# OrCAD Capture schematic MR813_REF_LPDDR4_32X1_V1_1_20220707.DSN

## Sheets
1 SOC: size A3; title: R818_REF_LPDDR4_32bitx1; rev: 0.1; note: SOC
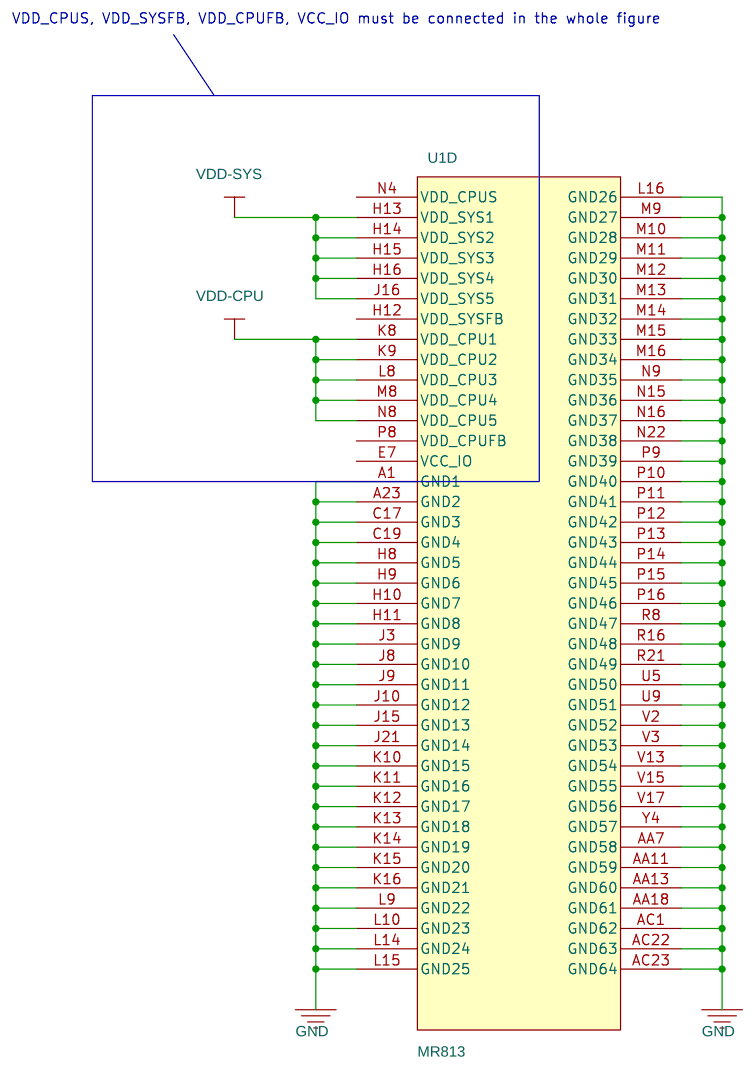
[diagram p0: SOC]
2 LPDDR4 32X1: size A3; title: A818_REF_LPDDR4_32bitx1; note: LPDDR4 32X1
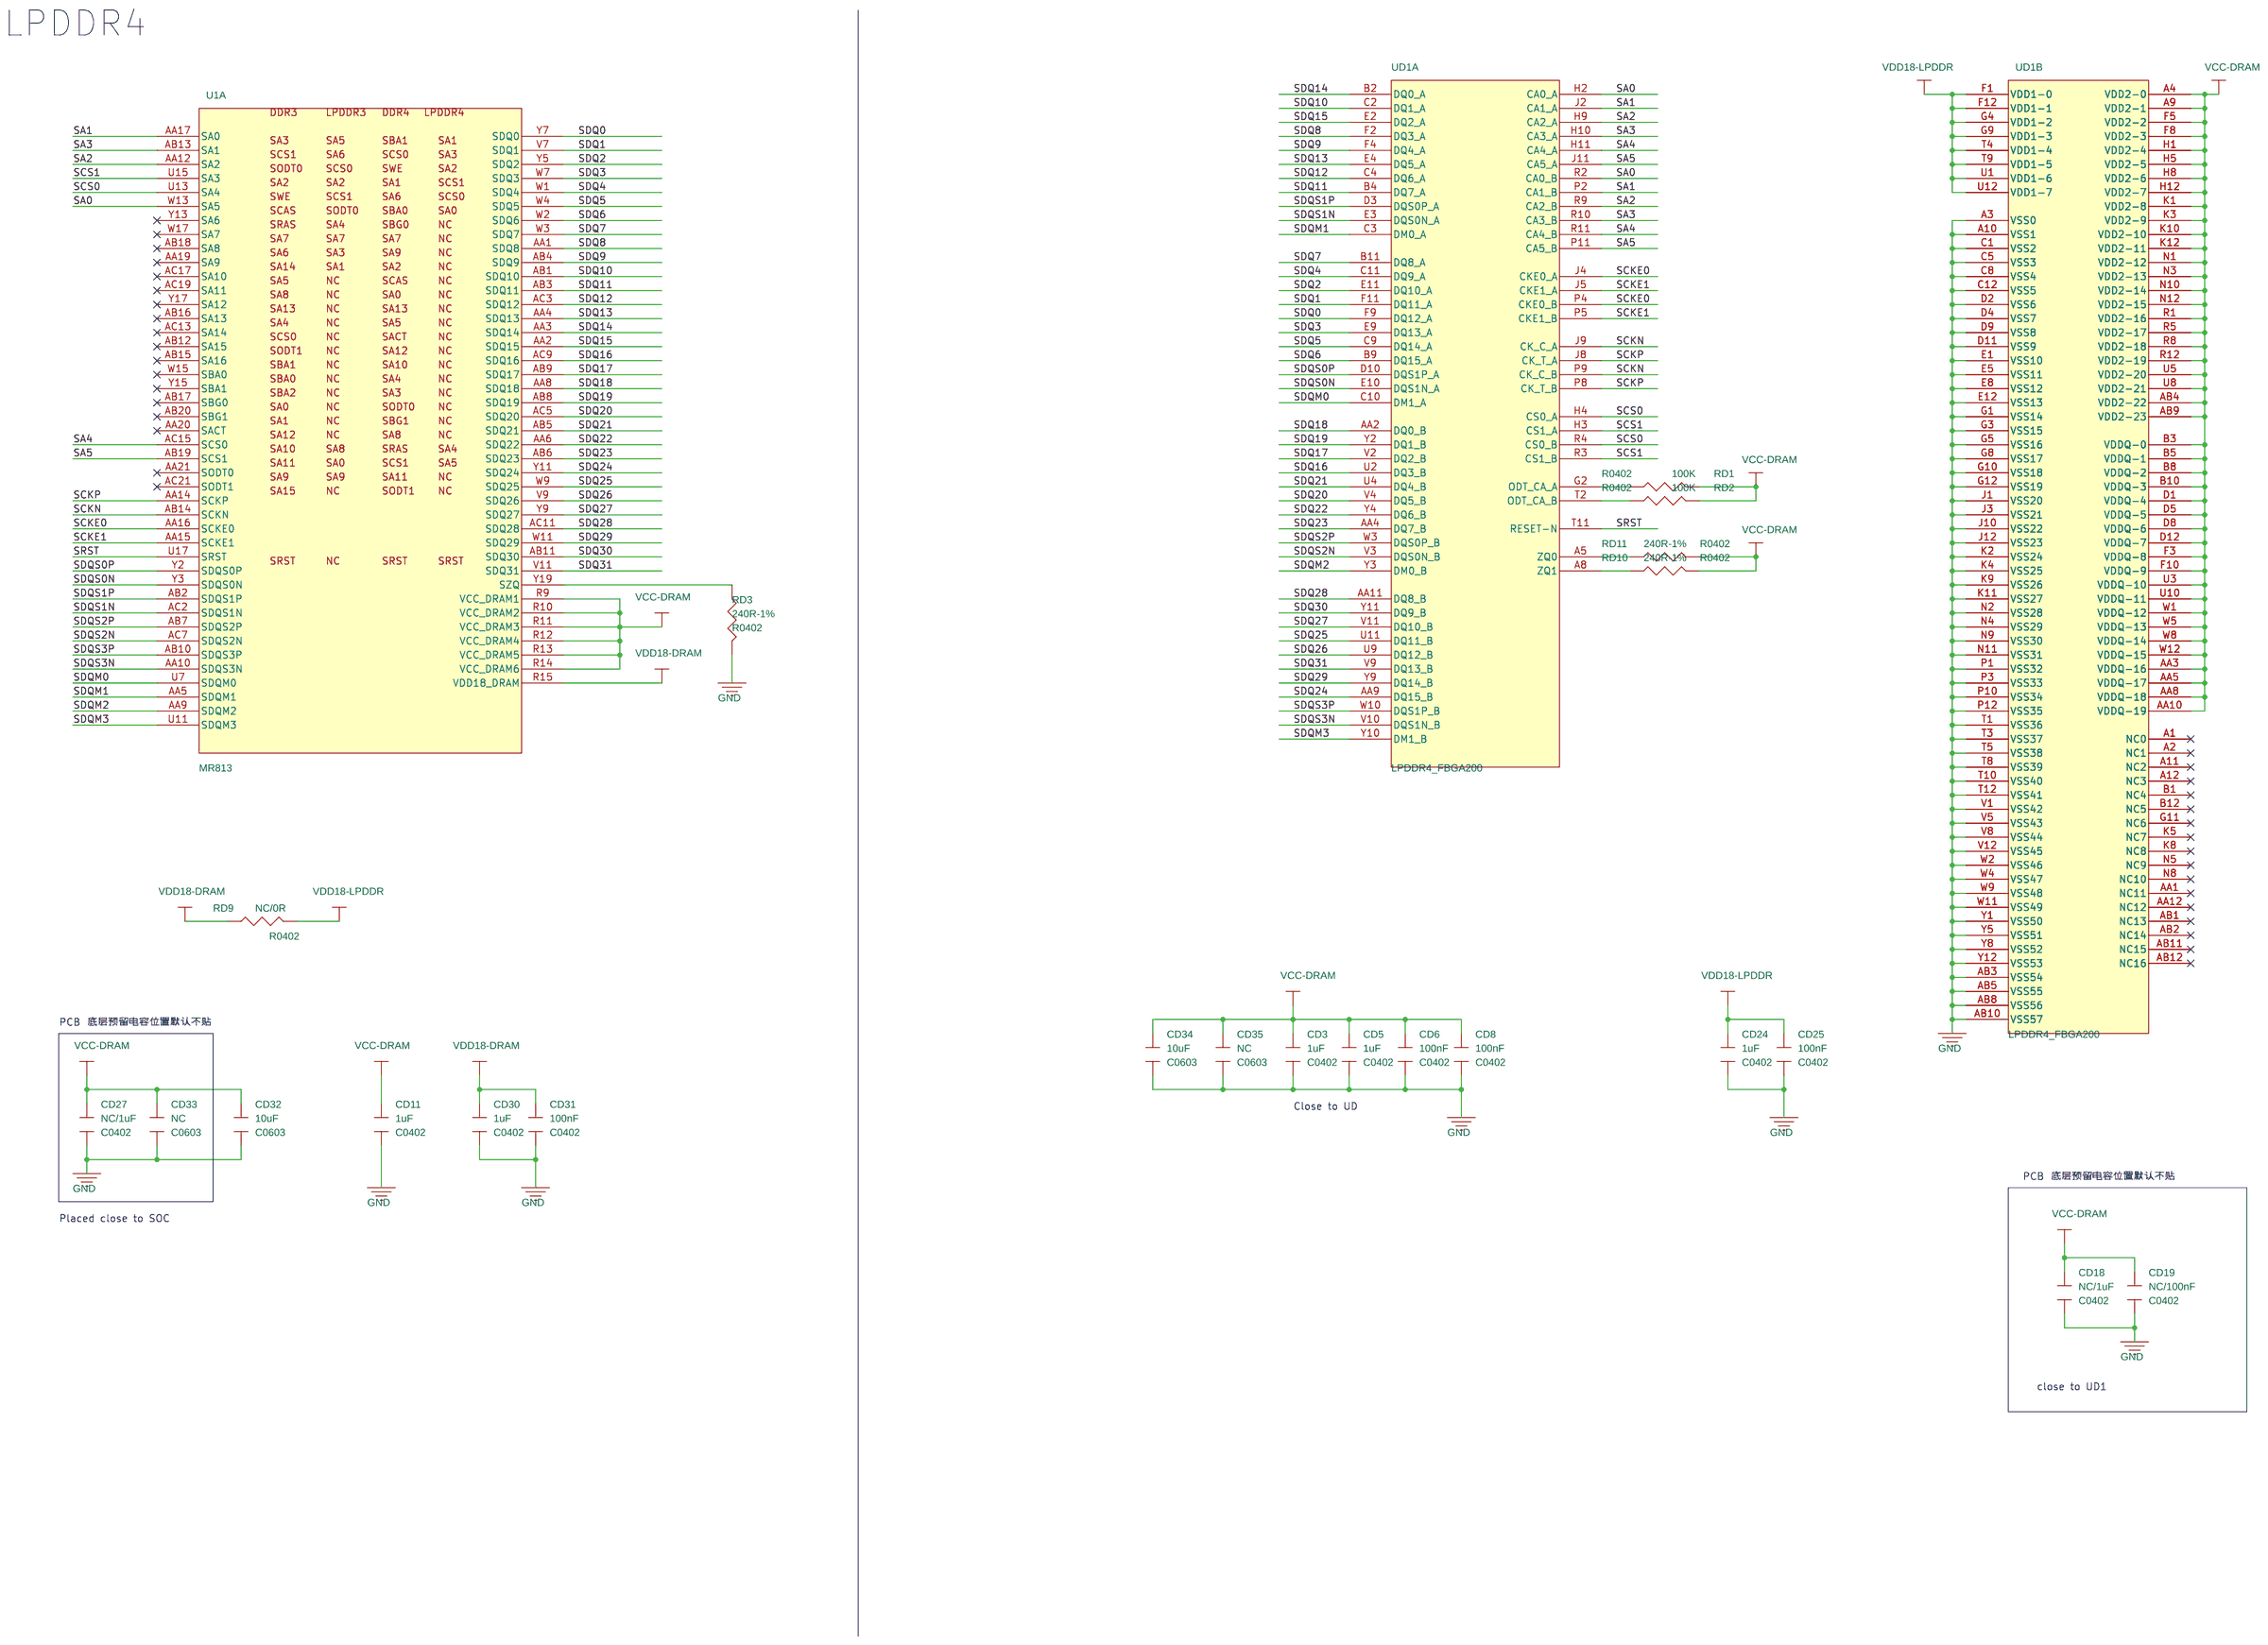
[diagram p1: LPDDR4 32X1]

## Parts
sheet LPDDR4 32X1
CD3  1uF  [C0402]
CD5  1uF  [C0402]
CD6  100nF  [C0402]
CD8  100nF  [C0402]
CD11  1uF  [C0402]
CD18  NC/1uF  [C0402]
CD19  NC/100nF  [C0402]
CD24  1uF  [C0402]
CD25  100nF  [C0402]
CD27  NC/1uF  [C0402]
CD30  1uF  [C0402]
CD31  100nF  [C0402]
CD32  10uF  [C0603]
CD33  NC  [C0603]
CD34  10uF  [C0603]
CD35  NC  [C0603]
RD1  100K  [R0402]
RD2  100K  [R0402]
RD3  240R-1%  [R0402]
RD9  NC/0R  [R0402]
RD10  240R-1%  [R0402]
RD11  240R-1%  [R0402]
UD1  LPDDR4_FBGA200  [BGA200P65_80B1000_1500H90]  (sections A,B)
sheet SOC
U1  MR813  [BGA346P50B1200_1200H114]  (sections A,D)

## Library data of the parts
CD3 CD5 CD6 CD8 CD11 CD18 CD19 CD24 CD25 CD27 CD30-CD35 = C-C0402: Parameter: C0402-X5R
RD1 RD2 = R-R0402-5%
RD3 RD9-RD11 = R-R0402-1%
UD1 = LPDDR4_FBGA200
U1 = R818-BGA-20200509

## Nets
GND: CD3.2 CD5.2 CD6.2 CD8.2 CD11.2 CD18.2 CD19.2 CD24.2 CD25.2 CD27.2 CD30.2 CD31.2 CD32.2 CD33.2 CD34.2 CD35.2 RD3.2 U1.A1(GND1) U1.A23(GND2) U1.AA7(GND58) U1.AA11(GND59) U1.AA13(GND60) U1.AA18(GND61) U1.AC1(GND62) U1.AC22(GND63) U1.AC23(GND64) U1.C17(GND3) U1.C19(GND4) U1.H8(GND5) U1.H9(GND6) U1.H10(GND7) U1.H11(GND8) U1.J3(GND9) U1.J8(GND10) U1.J9(GND11) U1.J10(GND12) U1.J15(GND13) U1.J21(GND14) U1.K10(GND15) U1.K11(GND16) U1.K12(GND17) U1.K13(GND18) U1.K14(GND19) U1.K15(GND20) U1.K16(GND21) U1.L9(GND22) U1.L10(GND23) U1.L14(GND24) U1.L15(GND25) U1.L16(GND26) U1.M9(GND27) U1.M10(GND28) U1.M11(GND29) U1.M12(GND30) U1.M13(GND31) U1.M14(GND32) U1.M15(GND33) U1.M16(GND34) U1.N9(GND35) U1.N15(GND36) U1.N16(GND37) U1.N22(GND38) U1.P9(GND39) U1.P10(GND40) U1.P11(GND41) U1.P12(GND42) U1.P13(GND43) U1.P14(GND44) U1.P15(GND45) U1.P16(GND46) U1.R8(GND47) U1.R16(GND48) U1.R21(GND49) U1.U5(GND50) U1.U9(GND51) U1.V2(GND52) U1.V3(GND53) U1.V13(GND54) U1.V15(GND55) U1.V17(GND56) U1.Y4(GND57) UD1.A3(VSS0) UD1.A10(VSS1) UD1.AB3(VSS54) UD1.AB5(VSS55) UD1.AB8(VSS56) UD1.AB10(VSS57) UD1.C1(VSS2) UD1.C5(VSS3) UD1.C8(VSS4) UD1.C12(VSS5) UD1.D2(VSS6) UD1.D4(VSS7) UD1.D9(VSS8) UD1.D11(VSS9) UD1.E1(VSS10) UD1.E5(VSS11) UD1.E8(VSS12) UD1.E12(VSS13) UD1.G1(VSS14) UD1.G3(VSS15) UD1.G5(VSS16) UD1.G8(VSS17) UD1.G10(VSS18) UD1.G12(VSS19) UD1.J1(VSS20) UD1.J3(VSS21) UD1.J10(VSS22) UD1.J12(VSS23) UD1.K2(VSS24) UD1.K4(VSS25) UD1.K9(VSS26) UD1.K11(VSS27) UD1.N2(VSS28) UD1.N4(VSS29) UD1.N9(VSS30) UD1.N11(VSS31) UD1.P1(VSS32) UD1.P3(VSS33) UD1.P10(VSS34) UD1.P12(VSS35) UD1.T1(VSS36) UD1.T3(VSS37) UD1.T5(VSS38) UD1.T8(VSS39) UD1.T10(VSS40) UD1.T12(VSS41) UD1.V1(VSS42) UD1.V5(VSS43) UD1.V8(VSS44) UD1.V12(VSS45) UD1.W2(VSS46) UD1.W4(VSS47) UD1.W9(VSS48) UD1.W11(VSS49) UD1.Y1(VSS50) UD1.Y5(VSS51) UD1.Y8(VSS52) UD1.Y12(VSS53)
VCC-DRAM: CD3.1 CD5.1 CD6.1 CD8.1 CD11.1 CD18.1 CD19.1 CD27.1 CD32.1 CD33.1 CD34.1 CD35.1 RD1.2 RD2.2 RD10.2 RD11.2 U1.R9(VCC_DRAM1) U1.R10(VCC_DRAM2) U1.R11(VCC_DRAM3) U1.R12(VCC_DRAM4) U1.R13(VCC_DRAM5) U1.R14(VCC_DRAM6) UD1.A4(VDD2-0) UD1.A9(VDD2-1) UD1.AA3(VDDQ-16) UD1.AA5(VDDQ-17) UD1.AA8(VDDQ-18) UD1.AA10(VDDQ-19) UD1.AB4(VDD2-22) UD1.AB9(VDD2-23) UD1.B3(VDDQ-0) UD1.B5(VDDQ-1) UD1.B8(VDDQ-2) UD1.B10(VDDQ-3) UD1.D1(VDDQ-4) UD1.D5(VDDQ-5) UD1.D8(VDDQ-6) UD1.D12(VDDQ-7) UD1.F3(VDDQ-8) UD1.F5(VDD2-2) UD1.F8(VDD2-3) UD1.F10(VDDQ-9) UD1.H1(VDD2-4) UD1.H5(VDD2-5) UD1.H8(VDD2-6) UD1.H12(VDD2-7) UD1.K1(VDD2-8) UD1.K3(VDD2-9) UD1.K10(VDD2-10) UD1.K12(VDD2-11) UD1.N1(VDD2-12) UD1.N3(VDD2-13) UD1.N10(VDD2-14) UD1.N12(VDD2-15) UD1.R1(VDD2-16) UD1.R5(VDD2-17) UD1.R8(VDD2-18) UD1.R12(VDD2-19) UD1.U3(VDDQ-10) UD1.U5(VDD2-20) UD1.U8(VDD2-21) UD1.U10(VDDQ-11) UD1.W1(VDDQ-12) UD1.W5(VDDQ-13) UD1.W8(VDDQ-14) UD1.W12(VDDQ-15)
VDD18-DRAM: CD30.1 CD31.1 RD9.1 U1.R15(VDD18_DRAM)
VDD18-LPDDR: CD24.1 CD25.1 RD9.2 UD1.F1(VDD1-0) UD1.F12(VDD1-1) UD1.G4(VDD1-2) UD1.G9(VDD1-3) UD1.T4(VDD1-4) UD1.T9(VDD1-5) UD1.U1(VDD1-6) UD1.U12(VDD1-7)
VDD-CPU: U1.K8(VDD_CPU1) U1.K9(VDD_CPU2) U1.L8(VDD_CPU3) U1.M8(VDD_CPU4) U1.N8(VDD_CPU5)
VDD-SYS: U1.H13(VDD_SYS1) U1.H14(VDD_SYS2) U1.H15(VDD_SYS3) U1.H16(VDD_SYS4) U1.J16(VDD_SYS5)
SA0: U1.W13(SA5) UD1.H2(CA0_A) UD1.R2(CA0_B)
SA1: U1.AA17(SA0) UD1.J2(CA1_A) UD1.P2(CA1_B)
SA2: U1.AA12(SA2) UD1.H9(CA2_A) UD1.R9(CA2_B)
SA3: U1.AB13(SA1) UD1.H10(CA3_A) UD1.R10(CA3_B)
SA4: U1.AC15(SCS0) UD1.H11(CA4_A) UD1.R11(CA4_B)
SA5: U1.AB19(SCS1) UD1.J11(CA5_A) UD1.P11(CA5_B)
SCKE0: U1.AA16(SCKE0) UD1.J4(CKE0_A) UD1.P4(CKE0_B)
SCKE1: U1.AA15(SCKE1) UD1.J5(CKE1_A) UD1.P5(CKE1_B)
SCKN: U1.AB14(SCKN) UD1.J9(CK_C_A) UD1.P9(CK_C_B)
SCKP: U1.AA14(SCKP) UD1.J8(CK_T_A) UD1.P8(CK_T_B)
SCS0: U1.U13(SA4) UD1.H4(CS0_A) UD1.R4(CS0_B)
SCS1: U1.U15(SA3) UD1.H3(CS1_A) UD1.R3(CS1_B)
SDQ0: U1.Y7(SDQ0) UD1.F9(DQ12_A)
SDQ1: U1.V7(SDQ1) UD1.F11(DQ11_A)
SDQ2: U1.Y5(SDQ2) UD1.E11(DQ10_A)
SDQ3: U1.W7(SDQ3) UD1.E9(DQ13_A)
SDQ4: U1.W1(SDQ4) UD1.C11(DQ9_A)
SDQ5: U1.W4(SDQ5) UD1.C9(DQ14_A)
SDQ6: U1.W2(SDQ6) UD1.B9(DQ15_A)
SDQ7: U1.W3(SDQ7) UD1.B11(DQ8_A)
SDQ8: U1.AA1(SDQ8) UD1.F2(DQ3_A)
SDQ9: U1.AB4(SDQ9) UD1.F4(DQ4_A)
SDQ10: U1.AB1(SDQ10) UD1.C2(DQ1_A)
SDQ11: U1.AB3(SDQ11) UD1.B4(DQ7_A)
SDQ12: U1.AC3(SDQ12) UD1.C4(DQ6_A)
SDQ13: U1.AA4(SDQ13) UD1.E4(DQ5_A)
SDQ14: U1.AA3(SDQ14) UD1.B2(DQ0_A)
SDQ15: U1.AA2(SDQ15) UD1.E2(DQ2_A)
SDQ16: U1.AC9(SDQ16) UD1.U2(DQ3_B)
SDQ17: U1.AB9(SDQ17) UD1.V2(DQ2_B)
SDQ18: U1.AA8(SDQ18) UD1.AA2(DQ0_B)
SDQ19: U1.AB8(SDQ19) UD1.Y2(DQ1_B)
SDQ20: U1.AC5(SDQ20) UD1.V4(DQ5_B)
SDQ21: U1.AB5(SDQ21) UD1.U4(DQ4_B)
SDQ22: U1.AA6(SDQ22) UD1.Y4(DQ6_B)
SDQ23: U1.AB6(SDQ23) UD1.AA4(DQ7_B)
SDQ24: U1.Y11(SDQ24) UD1.AA9(DQ15_B)
SDQ25: U1.W9(SDQ25) UD1.U11(DQ11_B)
SDQ26: U1.V9(SDQ26) UD1.U9(DQ12_B)
SDQ27: U1.Y9(SDQ27) UD1.V11(DQ10_B)
SDQ28: U1.AC11(SDQ28) UD1.AA11(DQ8_B)
SDQ29: U1.W11(SDQ29) UD1.Y9(DQ14_B)
SDQ30: U1.AB11(SDQ30) UD1.Y11(DQ9_B)
SDQ31: U1.V11(SDQ31) UD1.V9(DQ13_B)
SDQM0: U1.U7(SDQM0) UD1.C10(DM1_A)
SDQM1: U1.AA5(SDQM1) UD1.C3(DM0_A)
SDQM2: U1.AA9(SDQM2) UD1.Y3(DM0_B)
SDQM3: U1.U11(SDQM3) UD1.Y10(DM1_B)
SDQS0N: U1.Y3(SDQS0N) UD1.E10(DQS1N_A)
SDQS0P: U1.Y2(SDQS0P) UD1.D10(DQS1P_A)
SDQS1N: U1.AC2(SDQS1N) UD1.E3(DQS0N_A)
SDQS1P: U1.AB2(SDQS1P) UD1.D3(DQS0P_A)
SDQS2N: U1.AC7(SDQS2N) UD1.V3(DQS0N_B)
SDQS2P: U1.AB7(SDQS2P) UD1.W3(DQS0P_B)
SDQS3N: U1.AA10(SDQS3N) UD1.V10(DQS1N_B)
SDQS3P: U1.AB10(SDQS3P) UD1.W10(DQS1P_B)
SRST: U1.U17(SRST) UD1.T11(RESET-N)
N11792: RD3.1 U1.Y19(SZQ)
N120080: RD10.1 UD1.A8(ZQ1)
N120084: RD11.1 UD1.A5(ZQ0)
N121252: RD1.1 UD1.G2(ODT_CA_A)
N121256: RD2.1 UD1.T2(ODT_CA_B)

Not connected (* = marked no-connect by the designer): U1 AA19(SA9)* AA20(SACT)* AA21(SODT0)* AB12(SA15)* AB15(SA16)* AB16(SA13)* AB17(SBG0)* AB18(SA8)* AB20(SBG1)* AC13(SA14)* AC17(SA10)* AC19(SA11)* AC21(SODT1)* E7(VCC_IO) H12(VDD_SYSFB) N4(VDD_CPUS) P8(VDD_CPUFB) W15(SBA0)* W17(SA7)* Y13(SA6)* Y15(SBA1)* Y17(SA12)*; UD1 A1(NC0)* A2(NC1)* A11(NC2)* A12(NC3)* AA1(NC11)* AA12(NC12)* AB1(NC13)* AB2(NC14)* AB11(NC15)* AB12(NC16)* B1(NC4)* B12(NC5)* G11(NC6)* K5(NC7)* K8(NC8)* N5(NC9)* N8(NC10)*

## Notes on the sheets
sheet 1
- VDD_CPUS, VDD_SYSFB, VDD_CPUFB, VCC_IO must be connected in the whole figure
sheet 2
- LPDDR4
- PCB
- 底层预留电容位置默认不贴
- Close to UD
- PCB
- 底层预留电容位置默认不贴
- Placed close to SOC
- close to UD1
